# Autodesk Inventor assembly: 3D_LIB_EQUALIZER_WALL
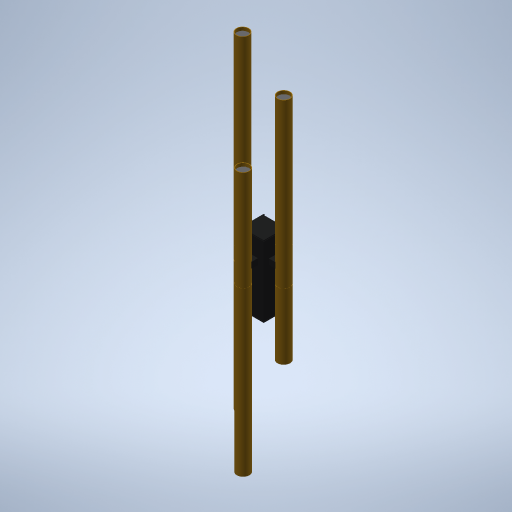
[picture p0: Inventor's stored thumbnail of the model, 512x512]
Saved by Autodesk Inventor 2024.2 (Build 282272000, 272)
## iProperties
Company: DARK
Created: 2024-07
Part Number: 3D_LIB_EQUALIZER_WALL
Document SubType Name: Assembly
Designer: Manuel
Project: 456 - EQUALIZER
Description: EQUALIZER Wall
Author: Manuel
Revision Number: v0
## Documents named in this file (14)
- C:\Users\Stage\Desktop\Stage Karsten\3D\Equalizer_KARSTEN\3D_LIB_EQUALIZER_WALL.iam
- C:\Users\Stage\Desktop\Stage Karsten\3D\EQUALIZER Wall\456-020.ipt
- C:\Users\Stage\Desktop\Stage Karsten\3D\EQUALIZER Wall\456-021.ipt
- C:\Users\Stage\Desktop\Stage Karsten\3D\EQUALIZER Wall\456-022.ipt
- C:\Users\Stage\Desktop\Stage Karsten\3D\EQUALIZER Wall\456-024.ipt
- C:\Users\Stage\Desktop\Stage Karsten\3D\EQUALIZER Wall\DIN 912 M3 x 16.ipt
- C:\Users\Stage\Desktop\Stage Karsten\3D\EQUALIZER Wall\DIN 916 M3 x 8.ipt
- C:\Users\Stage\Desktop\Stage Karsten\3D\EQUALIZER Wall\KGP CC15W xx TRIAC.ipt
- C:\Users\Stage\Desktop\Stage Karsten\3D\EQUALIZER Wall\4W LED mod.ipt
- C:\Users\Stage\Desktop\Stage Karsten\3D\EQUALIZER Wall\456-027.ipt
- C:\Users\Stage\Desktop\Stage Karsten\3D\EQUALIZER Wall\456-043.ipt
- C:\Users\Stage\Desktop\Stage Karsten\3D\EQUALIZER Wall\456-044.ipt
- C:\Users\Stage\Desktop\Stage Karsten\3D\EQUALIZER Wall\456-045.ipt
- C:\Users\Stage\Desktop\Stage Karsten\3D\EQUALIZER Wall\456-046.ipt
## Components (37 placed, 13 different names)
1. 456-020:1
2. 456-020:2
3. 456-020:3
4. 456-043:1
5. 456-044:1 — Flush:6, Mate:8, Mate:10, Flush:8
6. 456-044:2 — Flush:7, Flush:9, Mate:12
7. 456-044:3 — Flush:7, Flush:8, Flush:9, Mate:11, Mate:13
8. 456-021:1 — Mate:26, Mate:27, Mate:34, Mate:35
9. 456-022:1 — Mate:24, Mate:25, Mate:36, Mate:37
10. 456-046:1 — Mate:22, Mate:23, Mate:30, Mate:31, Mate:61, Mate:62
11. 456-024:1 — Mate:18, Mate:19
12. 456-024:2 — Mate:36, Mate:37
13. 456-024:3 — Mate:34, Mate:35
14. 456-024:4 — Mate:32, Mate:33
15. 456-024:5 — Mate:30, Mate:31
16. 456-021:6 — Mate:14, Mate:15, Mate:16, Mate:17
17. 456-022:6 — Mate:28, Mate:29, Mate:32, Mate:33, Mate:63, Mate:64
18. 456-046:2 — Mate:18, Mate:19, Mate:20, Mate:21, Mate:65, Mate:66
19. 456-024:6 — Mate:14, Mate:15
20. DIN 912 M3 x 16:1 — Flush:12, Mate:42
21. DIN 912 M3 x 16:2 — Flush:12, Mate:40, Mate:41
22. DIN 912 M3 x 16:3 — Flush:11, Mate:44
23. DIN 912 M3 x 16:4 — Flush:11, Mate:39, Mate:43
24. DIN 912 M3 x 16:5 — Flush:10, Mate:46
25. DIN 912 M3 x 16:6 — Flush:10, Mate:38, Mate:45
26. 456-045:1 — Flush:13, Flush:14, Mate:47, Mate:52, Mate:53, Mate:54
27. DIN 916 M3 x 8:1 — Flush:15, Mate:49, Mate:50
28. DIN 916 M3 x 8:2 — Flush:15, Angle:1, Mate:48, Flush:18
29. DIN 916 M3 x 8:3 — Flush:16, Mate:49, Angle:2
30. DIN 916 M3 x 8:4 — Flush:16, Angle:1, Mate:48, Mate:51, Flush:17
31. KGP CC15W xx TRIAC:1 — Mate:52, Mate:53, Mate:54
32. 4W LED mod:1 — Mate:59, Mate:60
33. 456-027:1 — Mate:59, Mate:60, Mate:61, Mate:62
34. 4W LED mod:2 — Mate:57, Mate:58
35. 456-027:2 — Mate:57, Mate:58, Mate:63, Mate:64
36. 4W LED mod:3 — Mate:55, Mate:56
37. 456-027:3 — Mate:55, Mate:56, Mate:65, Mate:66
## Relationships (73: Mate 58, Flush 13, Angle 2)
- Flush:6: 456-044:1
- Mate:8: 456-044:1
- Mate:10: 456-044:1
- Flush:7: 456-044:2 ↔ 456-044:3
- Flush:8: 456-044:1 ↔ 456-044:3
- Flush:9: 456-044:2 ↔ 456-044:3
- Mate:11: 456-044:3
- Mate:12: 456-044:2
- Mate:13: 456-044:3
- Mate:14: 456-021:6 ↔ 456-024:6
- Mate:15: 456-021:6 ↔ 456-024:6
- Mate:16: 456-021:6
- Mate:17: 456-021:6
- Mate:18: 456-024:1 ↔ 456-046:2
- Mate:19: 456-024:1 ↔ 456-046:2
- Mate:20: 456-046:2
- Mate:21: 456-046:2
- Mate:22: 456-046:1
- Mate:23: 456-046:1
- Mate:24: 456-022:1
- Mate:25: 456-022:1
- Mate:26: 456-021:1
- Mate:27: 456-021:1
- Mate:28: 456-022:6
- Mate:29: 456-022:6
- Mate:30: 456-046:1 ↔ 456-024:5
- Mate:31: 456-046:1 ↔ 456-024:5
- Mate:32: 456-024:4 ↔ 456-022:6
- Mate:33: 456-024:4 ↔ 456-022:6
- Mate:34: 456-021:1 ↔ 456-024:3
- Mate:35: 456-021:1 ↔ 456-024:3
- Mate:36: 456-022:1 ↔ 456-024:2
- Mate:37: 456-022:1 ↔ 456-024:2
- Flush:10: DIN 912 M3 x 16:5 ↔ DIN 912 M3 x 16:6
- Flush:11: DIN 912 M3 x 16:3 ↔ DIN 912 M3 x 16:4
- Flush:12: DIN 912 M3 x 16:1 ↔ DIN 912 M3 x 16:2
- Mate:38: DIN 912 M3 x 16:6
- Mate:39: DIN 912 M3 x 16:4
- Mate:40: DIN 912 M3 x 16:2
- Mate:41: DIN 912 M3 x 16:2
- Mate:42: DIN 912 M3 x 16:1
- Mate:43: DIN 912 M3 x 16:4
- Mate:44: DIN 912 M3 x 16:3
- Mate:45: DIN 912 M3 x 16:6
- Mate:46: DIN 912 M3 x 16:5
- Flush:13: 456-045:1
- Flush:14: 456-045:1
- Mate:47: 456-045:1
- Flush:15: DIN 916 M3 x 8:1 ↔ DIN 916 M3 x 8:2
- Flush:16: DIN 916 M3 x 8:3 ↔ DIN 916 M3 x 8:4
- Angle:1: DIN 916 M3 x 8:2 ↔ DIN 916 M3 x 8:4
- Mate:48: DIN 916 M3 x 8:2 ↔ DIN 916 M3 x 8:4
- Mate:49: DIN 916 M3 x 8:1 ↔ DIN 916 M3 x 8:3
- Angle:2: DIN 916 M3 x 8:3
- Mate:50: DIN 916 M3 x 8:1
- Mate:51: DIN 916 M3 x 8:4
- Flush:17: DIN 916 M3 x 8:4
- Flush:18: DIN 916 M3 x 8:2
- Mate:52: 456-045:1 ↔ KGP CC15W xx TRIAC:1
- Mate:53: 456-045:1 ↔ KGP CC15W xx TRIAC:1
- Mate:54: 456-045:1 ↔ KGP CC15W xx TRIAC:1
- Mate:55: 4W LED mod:3 ↔ 456-027:3
- Mate:56: 4W LED mod:3 ↔ 456-027:3
- Mate:57: 4W LED mod:2 ↔ 456-027:2
- Mate:58: 4W LED mod:2 ↔ 456-027:2
- Mate:59: 4W LED mod:1 ↔ 456-027:1
- Mate:60: 4W LED mod:1 ↔ 456-027:1
- Mate:61: 456-046:1 ↔ 456-027:1
- Mate:62: 456-046:1 ↔ 456-027:1
- Mate:63: 456-022:6 ↔ 456-027:2
- Mate:64: 456-022:6 ↔ 456-027:2
- Mate:65: 456-046:2 ↔ 456-027:3
- Mate:66: 456-046:2 ↔ 456-027:3
